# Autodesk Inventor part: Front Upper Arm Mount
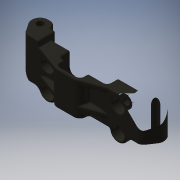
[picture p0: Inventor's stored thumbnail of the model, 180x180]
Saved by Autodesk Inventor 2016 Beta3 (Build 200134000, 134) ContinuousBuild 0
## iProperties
Shininess: 41.0
Compacted: True
Length Units: 11272
Angle Units: 11279
Time Units: 11290
Mass Units: 11286
Length Display Precision: 3
Angle Display Precision: 2
Company: Autodesk
Created: 2001-02
Part Number: Front Upper Arm Mount
Document SubType Name: Modeling
Designer: Autodesk, Inc.
Material: Stiffzel
Project: Inventor Samples
Density: 1.28 g/cm^3
Mass: 8.2438 g
Surface Area: 43.7502 cm^2
Volume: 6.44047 cm^3
Appearance: Stiffzel
Density: 0.0
Volumn: 0.0
Area: 0.0
PropertySet Name: Model Information
Control State: 0
Master: False
Checked Out: False
Author: Autodesk, Inc.
Revision Number: A
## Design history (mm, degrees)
sketch "Sketch1"
  geometry: L1 (20.137, 81.089)-(30.678, 81.089); L2 (30.678, 81.089)-(30.678, 100.139); L3 (30.678, 100.139)-(20.137, 100.139); L4 (20.137, 100.139)-(20.137, 81.089); L5 (-21.011, 81.089)-(-31.552, 81.089); L6 (-31.552, 81.089)-(-31.552, 100.139); L7 (-31.552, 100.139)-(-21.011, 100.139); L8 (-21.011, 100.139)-(-21.011, 81.089)
  constraints: 16 end point, 4 parallel, 3 collinear, 2 horizontal, 2 perpendicular
  dimensions: "d0" = 41.148 distance between parallel lines of L4 L8; "d1" = 10.541 distance of L2.end L3.end; "d2" = 19.05 distance of L1.end L2.end
extrude "Extrusion1" new body sketch "Sketch1" distance "d3" = 8.001; taper "d4" = 0 deg
sketch "Sketch15"
  geometry: L1 (21.011, 81.089)-(31.552, 81.089) reference; L2 (31.552, 100.139)-(23.551, 100.139); L3 (23.551, 100.139)-(23.551, 81.089); L4 (23.551, 81.089)-(31.552, 81.089); L5 (31.552, 81.089)-(31.552, 100.139); L6 (-30.678, 81.089)-(-30.678, 100.139) reference; L7 (-30.678, 100.139)-(-20.137, 100.139) reference; L8 (-30.678, 81.089)-(-20.137, 81.089) reference; L9 (-22.677, 100.139)-(-22.677, 81.089)
  constraints: 10 end point, 3 point on line, 2 parallel, 2 perpendicular, 1 horizontal
  dimensions: "d81" = 8.001 distance between parallel lines of L5 L3 (= d3); "d82" = 8.001 distance between parallel lines of L9 L6 (= d3)
extrude "Extrusion12" join sketch "Sketch15" distance "d83" = 3.175; taper "d84" = 0 deg
fillet "Fillet1" dims "d5" = 4.0005 (= 0.5 x d3)
sketch "Sketch16"
  geometry: L1 (0, 0)-(0, 7.176) reference; L2 (0, 0)-(10.541, 0) reference; L3 (8.001, 11.176)-(4.001, 11.176) reference; L4 (62.23, 7.176)-(62.23, 0) reference; L5 (51.689, 0)-(62.23, 0) reference; L6 (0.679, 4.945)-(4.001, 0); L7 (61.551, 4.945)-(58.229, 0); A1 r 4.001 centre (4.001, 7.176) between (4.001, 11.176) and (0, 7.176) reference; A2 r 4.001 centre (58.229, 7.176) between (62.23, 7.176) and (58.229, 11.176) reference; A3 r 4.001 centre (58.229, 7.176) between (61.551, 4.945) and (62.23, 7.176); A4 r 4.001 centre (4.001, 7.176) between (4.001, 11.176) and (0.679, 4.945); 1 further point
  constraints: 6 point on circle, 5 end point, 3 coincident, 2 centre point, 2 point on line, 2 tangent, 2 vertical alignment
extrude "Extrusion13" cut sketch "Sketch16" stored distance "d85" = 2.54; taper "d86" = 0 deg
sketch "Sketch2"
  geometry: L1 (-21.011, 100.139)-(-21.011, 81.089) reference; L2 (20.137, 81.089)-(20.137, 100.139) reference; L3 (20.137, 81.089)-(-21.011, 81.089); L4 (-21.011, 81.089)-(-21.011, 97.281); L5 (-21.011, 97.281)-(20.137, 97.281); L6 (20.137, 97.281)-(20.137, 81.089)
  constraints: 8 end point, 2 parallel, 1 horizontal, 1 perpendicular, 1 point on line
  dimensions: "d6" = 16.1925 distance between parallel lines of L3 L5
extrude "Extrusion2" join sketch "Sketch2" distance "d7" = 6.35; taper "d8" = 0 deg
sketch "Sketch3"
  geometry: L1 (20.137, 97.281)-(20.137, 100.139) reference; L2 (-21.011, 100.139)-(-21.011, 97.281) reference; L3 (26.677, 81.089)-(-27.552, 81.089) reference; C1 r 4.001 at (16.136, 81.089); C2 r 4.001 at (-17.011, 81.089)
  constraints: 2 centre point, 2 point on line, 2 tangent, 1 equal radius
  dimensions: "d9" = 8.001 diameter of C1
extrude "Extrusion3" join sketch "Sketch3" distance "d10" = 6.35 (= d7); taper "d11" = 0 deg
fillet "Fillet2" dims "d12" = 3.175
sketch "Sketch4"
  geometry: L1 (41.148, 6.35)-(0, 6.35) reference; L2 (41.148, 0)-(0, 0) reference; L3 (41.148, 6.35)-(41.148, 0) reference; L4 (23.559, 0)-(23.559, -1.016); L5 (20.384, -4.191)-(12.764, -4.191); L6 (9.589, -1.016)-(9.588, 0); L7 (8.001, 0)-(8.001, 6.35) reference; A1 r 3.175 centre (20.384, -1.016) between (20.384, -4.191) and (23.559, -1.016); A2 r 3.175 centre (12.764, -1.016) between (9.589, -1.016) and (12.764, -4.191)
  constraints: 6 end point, 4 point on circle, 4 tangent, 2 centre point, 2 perpendicular, 2 point on line, 1 equal radius, 1 parallel
  dimensions: "d13" = 3.175 radius of A1; "d14" = 10.541 distance between parallel lines of L1 L5; "d15" = 13.97 distance between parallel lines of L6 L4; "d17" = 1.5875 distance between parallel lines of L7 L6
extrude "Extrusion4" join sketch "Sketch4" stored distance "d18" = 25.4; taper "d19" = 0 deg
sketch "Sketch5"
  geometry: L1 (9.588, -6.35)-(0, -6.35) reference; L2 (9.588, -6.35)-(9.589, -7.366) reference; L3 (23.559, -7.366)-(23.559, -6.35) reference; L4 (41.148, -6.35)-(23.559, -6.35) reference; L5 (11.668, -10.346)-(0.794, -6.35); L6 (21.479, -10.346)-(32.353, -6.35); A1 r 3.175 centre (12.764, -7.366) between (9.589, -7.366) and (12.764, -10.541) reference; A2 r 3.175 centre (20.384, -7.366) between (20.384, -10.541) and (23.559, -7.366) reference
  constraints: 4 end point, 2 point on circle, 2 tangent, 1 midpoint, 1 point on line
  dimensions: "d20" = 10.87462 horizontal distance of L6.start L6.end (derived); "d21" = 10.87462 horizontal distance of L5.start L5.end (= d20)
extrude "Extrusion5" join sketch "Sketch5" distance "d22" = 2.54; taper "d23" = 0 deg
sketch "Sketch6"
  geometry: L1 (41.148, 0)-(0, 0) reference; L2 (12.764, -10.541)-(20.384, -10.541) reference; L3 (9.588, -6.35)-(9.589, -7.366) reference; L4 (12.764, -10.541)-(20.384, -10.541) reference; L5 (23.559, -7.366)-(23.559, -6.35) reference; L6 (21.971, 0)-(21.971, -7.366); L7 (20.384, -8.954)-(12.764, -8.954); L8 (11.176, -7.366)-(11.176, 0); A1 r 3.175 centre (12.764, -7.366) between (9.589, -7.366) and (12.764, -10.541) reference; A2 r 3.175 centre (20.384, -7.366) between (20.384, -10.541) and (23.559, -7.366) reference; A3 r 1.587 centre (20.384, -7.366) between (20.384, -8.954) and (21.971, -7.366); A4 r 1.588 centre (12.764, -7.366) between (11.176, -7.366) and (12.764, -8.954)
  constraints: 6 end point, 4 point on circle, 4 tangent, 2 centre point, 2 concentric, 2 parallel, 2 point on line, 1 perpendicular
  dimensions: "d24" = 1.5875 distance between parallel lines of L2 L7
extrude "Extrusion6" cut sketch "Sketch6" stored distance "d25" = 2.54; taper "d26" = 0 deg
pattern_linear "Rectangular Pattern1" dims "d29" = 10.541
fillet "Fillet21" dims "d87" = 3.175
fillet "Fillet4" dims "d31" = 0.381
fillet "Fillet5" dims "d32" = 0.8128
sketch "Sketch7"
  geometry: C1 r 2.921 at (-17.011, 81.089); A1 r 4.001 centre (-17.011, 81.089) between (-20.598, 79.319) and (-13.01, 81.089) reference
  constraints: 1 centre point, 1 coincident
  dimensions: "d33" = 5.842 diameter of C1
extrude "Extrusion7" cut sketch "Sketch7" distance "d34" = 3.81; taper "d35" = 0 deg
sketch "Sketch8"
  geometry: C1 r 2.921 at (16.136, 81.089); A1 r 4.001 centre (16.136, 81.089) between (12.136, 81.089) and (19.724, 79.319) reference
  constraints: 1 centre point, 1 coincident
  dimensions: "d36" = 5.842 diameter of C1
extrude "Extrusion8" cut sketch "Sketch8" distance "d37" = 3.81 (= d34); taper "d38" = 0 deg
fillet "Fillet6" dims "d39" = 0.8128
fillet "Fillet8" dims "d41" = 0.8128
fillet "Fillet9" dims "d42" = 0.8128
fillet "Fillet22" dims "d88" = 3.175
fillet "Fillet10" dims "d43" = 0.8128
fillet "Fillet11" dims "d44" = 0.762
fillet "Fillet12" dims "d45" = 0.7874
fillet "Fillet13" dims "d46" = 0.7874
fillet "Fillet14" dims "d47" = 0.7874
fillet "Fillet15" dims "d48" = 0.7874
workplane "Work Plane1"
sketch "Sketch9"
  geometry: L1 (9.569, -3.746)-(0.532, -3.746); L2 (0, -0.825)-(7.62, -0.826) reference
  constraints: 2 end point, 1 horizontal
  dimensions: "d50" = 2.921 distance between parallel lines of L2 L1
feature "Rib1" sketch "Sketch9" dims "d51" = 2.54, "d52" = 2.54
fillet "Fillet16" dims "d53" = 0.7874
fillet "Fillet17" dims "d54" = 0.7874
pattern_linear "Rectangular Pattern2" dims "d57" = 11.049
sketch "Sketch10"
  geometry: C1 r 2.921 at (0, 0) reference
extrude "Extrusion9" cut sketch "Sketch10" stored distance "d58" = 3.81 (= d34); taper "d59" = 0 deg
fillet "Fillet18" dims "d60" = 0.381
sketch "Sketch11"
  geometry: C1 r 2.921 at (0, 0) reference; C2 r 2.921 at (33.147, 0) reference; C3 r 2.921 at (33.147, -11.049) reference; C4 r 2.921 at (0, -11.049) reference; 4 further points
  constraints: 4 coincident
hole "Hole1" sketch "Sketch11" at (0, -11.049), (33.147, 0), (33.147, -11.049), (0, 0) diameter "d61" = 3.175; stored, may be unused: countersink angle "d65" = 60 deg, drill point angle "d67" = 118 deg; dims "d62" = 12.7, "d63" = 9.525, "d64" = 6.35, "d66" = 19.05
sketch "Sketch12"
  geometry: 8 further points
  constraints: 2 coincident, 2 other
hole "Hole2" sketch "Sketch12" at (5.728, -0.063), (-48.501, -0.064) diameter "d68" = 3.175; stored, may be unused: countersink angle "d72" = 60 deg, drill point angle "d74" = 118 deg; dims "d69" = 12.7, "d70" = 9.525, "d71" = 6.35, "d73" = 19.05
workaxis "Work Axis1"
sketch "Sketch13"
  geometry: C1 r 17.399 at (-12.529, 4.432); 1 further point
  constraints: 1 centre point, 1 coincident
extrude "Extrusion10" cut sketch "Sketch13" distance "d75" = 8.89; taper "d76" = 0 deg
sketch "Sketch14"
  geometry: C1 r 17.399 at (19.082, 4.432); A1 r 17.399 centre (19.082, 4.432) between (2.064, 0.813) and (7.366, -8.431) reference; 1 further point
  constraints: 1 centre point, 1 coincident, 1 concentric
extrude "Extrusion11" cut sketch "Sketch14" distance "d79" = 2.54; taper "d80" = 0 deg
fillet "Fillet19" dims "d77" = 1.5875
fillet "Fillet20" dims "d78" = 0.8128
fillet "Fillet23" dims "d89" = 0.762 (derived)
body "Solid1"
other parameters: "d49" = -3.175, "d90" = 0, "d91" = 0, "d92" = 0, "d93" = 0
